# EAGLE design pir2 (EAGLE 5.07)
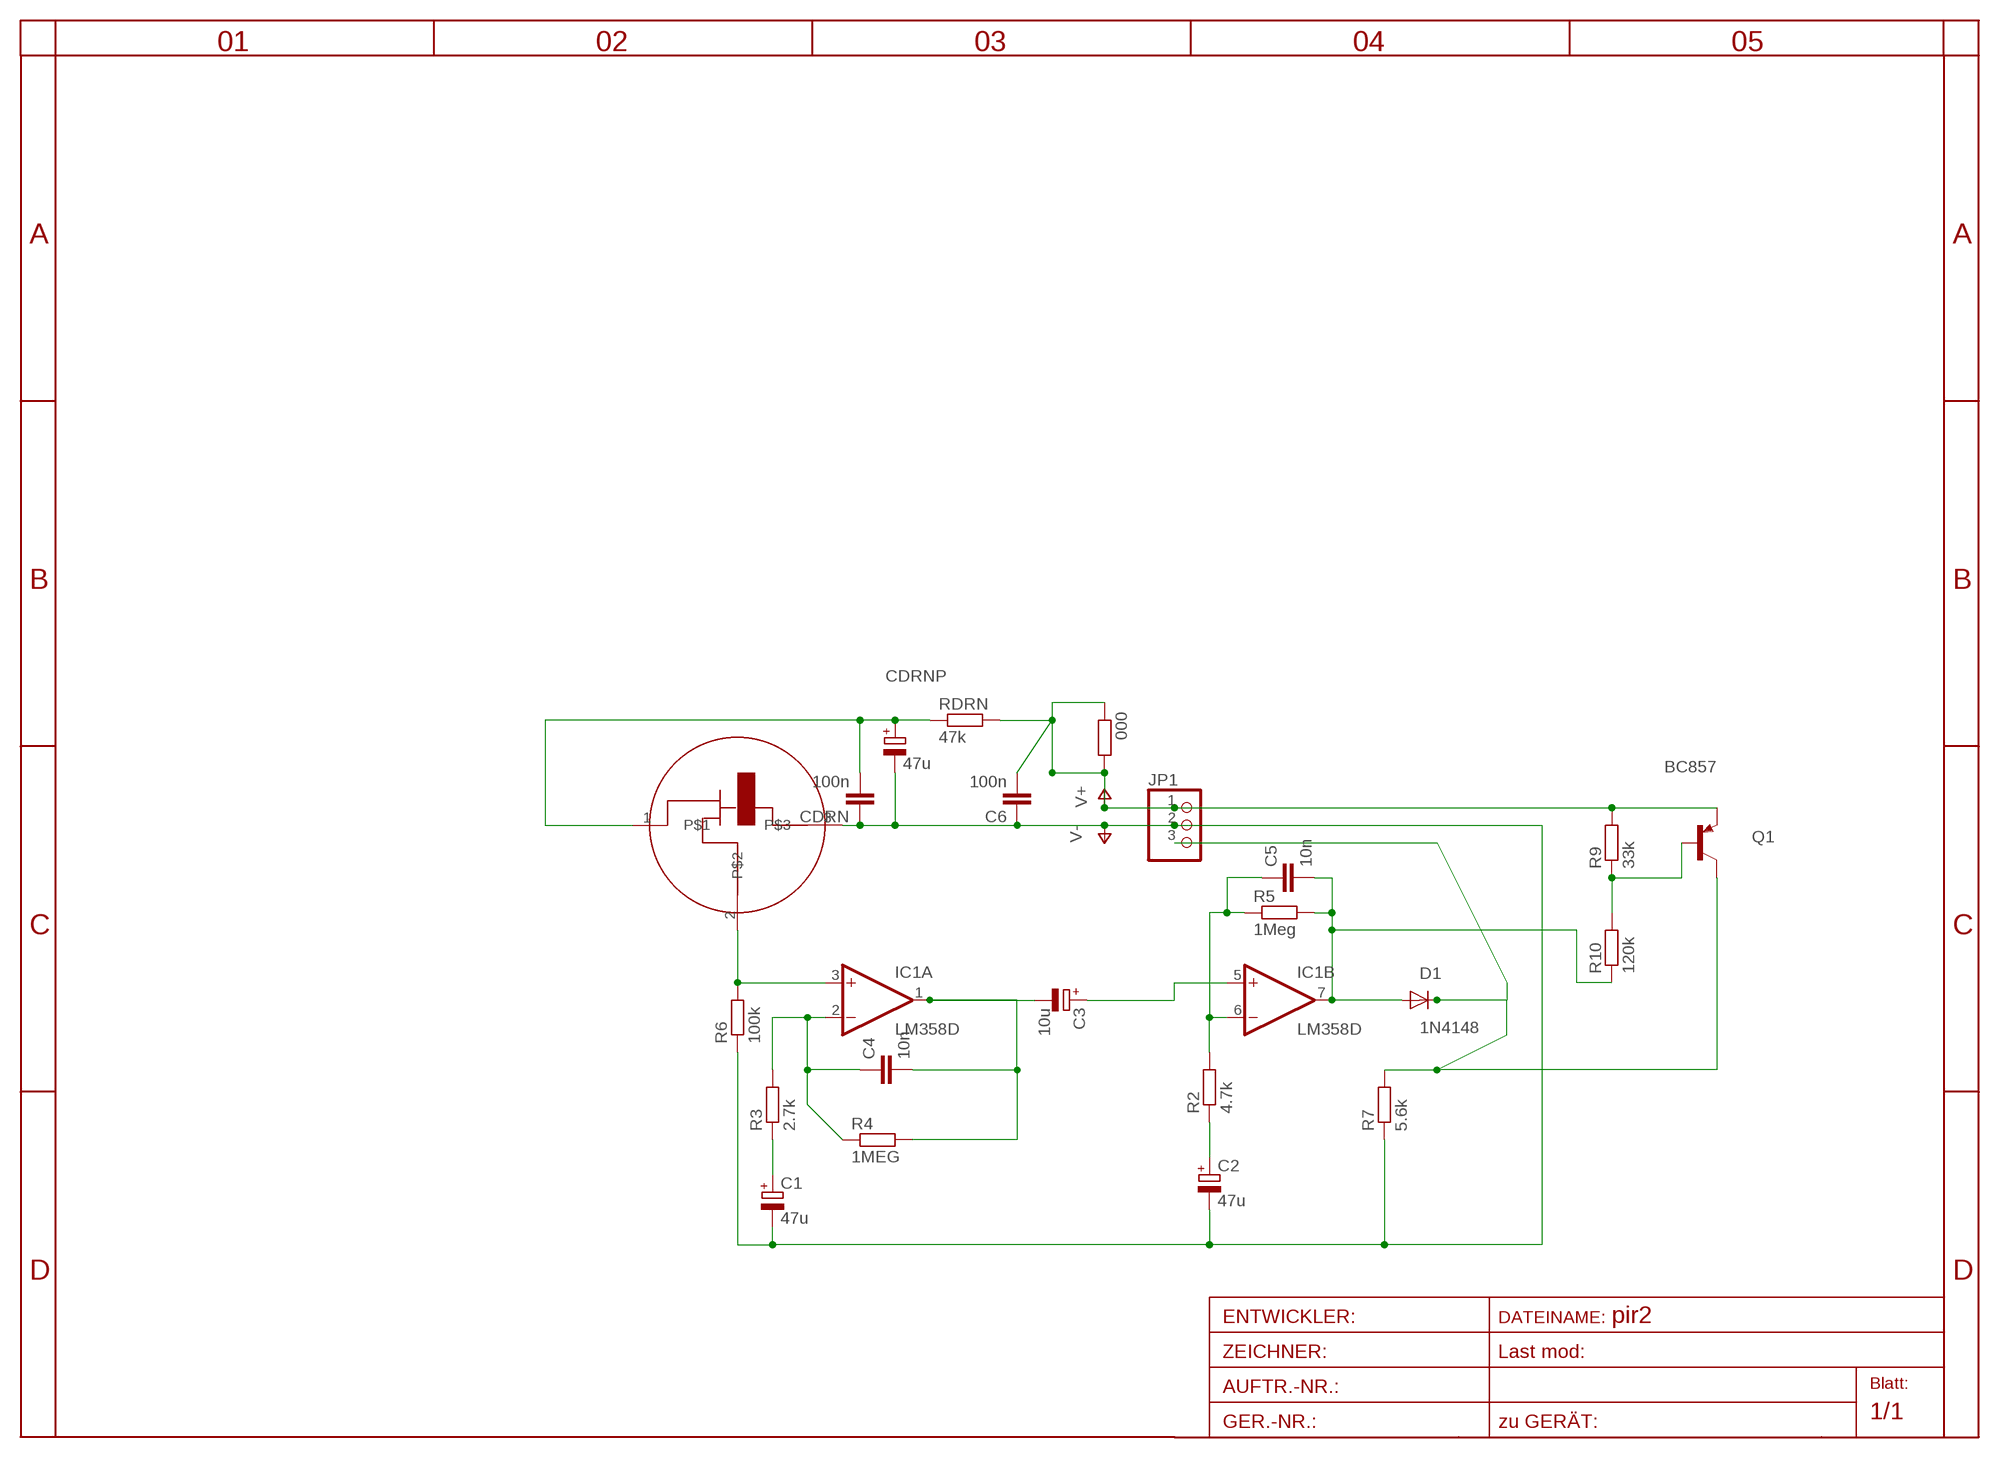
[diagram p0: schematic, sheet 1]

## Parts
000  R-EU_R1206  [R1206]
C1  47u  CPOL-EUTT2D4L  [TT2D4L]
C2  47u  CPOL-EUE2.5-5  [E2,5-5]
C3  10u  CPOL-EUE2.5-5  [E2,5-5]
C4  10n  C-EUC0805  [C0805]
C5  10n  C-EUC0805  [C0805]
C6  100n  C-EUC0805  [C0805]
CDRN  100n  C-EUC1206  [C1206]
CDRNP  47u  CPOL-EUE2.5-5  [E2,5-5]
D1  1N4148  1N4148MINIMELF  [MINIMELF]
IC1  LM358D  [SO08]
JP1  PINHD-1X3  [1X03]
PIR  RE200B  [R200B]
Q1  BC857  BC857ALT1SMD  [SOT23-BEC]
R2  4.7k  R-EU_R0805  [R0805]
R3  2.7k  R-EU_R1206  [R1206]
R4  1MEG  R-EU_R0805  [R0805]
R5  1Meg  R-EU_R0805  [R0805]
R6  100k  R-EU_R0805  [R0805]
R7  5.6k  R-EU_R0805  [R0805]
R9  33k  R-EU_R0805  [R0805]
R10  120k  R-EU_R1206  [R1206]
RDRN  47k  R-EU_R0805  [R0805]

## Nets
DRN: CDRN.2 CDRNP.+ PIR.1 RDRN.1
N$1: C5.2 D1.A IC1.7(B:OUT) R5.2 R10.1
N$4: IC1.3(A:+IN) PIR.2 R6.2
N$5: C4.1 IC1.2(A:-IN) R3.2 R4.1
N$6: C1.+ R3.1
N$7: C3.- C4.2 IC1.1(A:OUT) R4.2
N$8: C3.+ IC1.5(B:+IN)
N$9: C5.1 IC1.6(B:-IN) R2.2 R5.1
N$10: C2.+ R2.1
N$12: Q1.B R9.1 R10.2
SIGNAL: D1.C JP1.3 Q1.C R7.2
V+: 000.1 000.2 C6.2 JP1.1 Q1.E R9.2 RDRN.2
V-: C1.- C2.- C6.1 CDRN.1 CDRNP.- JP1.2 PIR.3 R6.1 R7.1

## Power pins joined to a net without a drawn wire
V+: IC1.8(P:V+)
V-: IC1.4(P:V-)

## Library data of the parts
000 R2-R7 R9 R10 RDRN = rcl:R-EU_: RESISTOR, European symbol
C1-C3 CDRNP = rcl:CPOL-EU: POLARIZED CAPACITOR, European symbol
C4-C6 CDRN = rcl:C-EU: CAPACITOR, European symbol
D1 = diode-1:1N4148: DIODE
IC1 = linear:LM358: OP AMP also LM158; LM258; LM2904 Source: http://cache.national.com/ds/LM/LM158.pdf
JP1 = pinhead:PINHD-1X3: PIN HEADER
PIR = photo-elements:RE200B
Q1 = transistor-pnp:BC857*: PNP Transistror

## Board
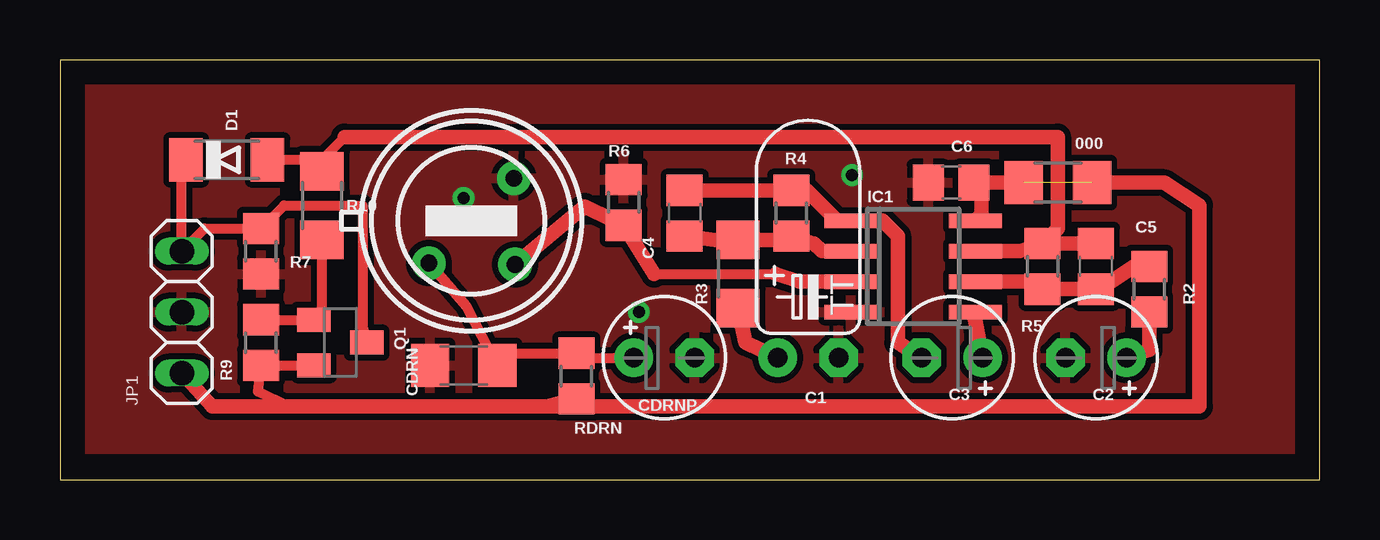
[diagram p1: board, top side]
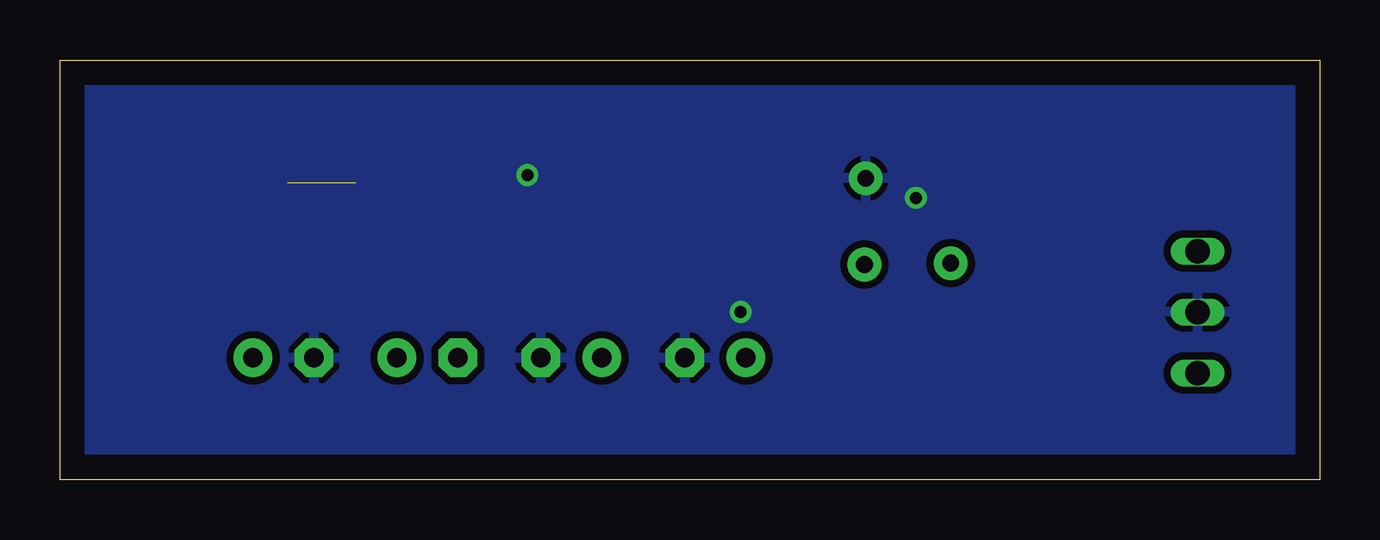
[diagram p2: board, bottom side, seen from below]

Size 52.5 x 17.5 mm. Coordinates in mm from the lower left corner, seen from the top.
Outline: 0,0 52.5,0 52.5,17.5 0,17.5 0,0
Copper layers (1*16): Top 0.035mm / dielectric 1.5mm / Bottom 0.035mm
Design rules "default": minimum track width 10mil, minimum drill 20mil, track to track 8mil, track to pad 8mil, pad to pad 8mil, via to via 8mil, smd to smd 8mil, copper to edge 40mil, drill to drill 8mil, minimum pad ring 1mil, minimum via ring 8mil, stop-mask expansion 4mil, vias tented up to drill 0mil, thermal gap 10mil

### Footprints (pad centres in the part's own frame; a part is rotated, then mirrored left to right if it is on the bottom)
R1206 = smd 1.6 x 1.803: 1 -1.422,0; 2 1.422,0
TT2D4L = drill 0.813 pad 1.6 round: + -1.27,0 | drill 0.813 pad 1.6 octagon: - 1.27,0
E2,5-5 = drill 0.813 pad 1.6 round: + -1.27,0 | drill 0.813 pad 1.6 octagon: - 1.27,0
C0805 = smd 1.3 x 1.5: 1 -0.95,0; 2 0.95,0
C1206 = smd 1.6 x 1.8: 1 -1.4,0; 2 1.4,0
MINIMELF = smd 1.4 x 1.8: A 1.7,0; C -1.7,0
SO08 = smd 0.6 x 2.2: 1 -1.905,-2.6; 2 -0.635,-2.6; 3 0.635,-2.6; 4 1.905,-2.6; 5 1.905,2.6; 6 0.635,2.6; 7 -0.635,2.6; 8 -1.905,2.6
1X03 = drill 1.016 long: 1 -2.54,0; 2 0,0; 3 2.54,0
R200B = drill 0.7 pad 1.4 round: 1 -2.5,0; 2 0,-2.58; 3 2.5,0
SOT23-BEC = smd 1 x 1.4: B -0.95,-1.1; C 0,1.1; E 0.95,-1.1
R0805 = smd 1.3 x 1.5: 1 -0.95,0; 2 0.95,0

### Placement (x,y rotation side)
000  41.59,12.38 180 top
C1  31.18,5.08 0 top
C2  43.18,5.08 180 top
C3  37.18,5.08 180 top
C4  26.04,11.11 90 top
C5  43.18,8.89 90 top
C6  37.15,12.38 0 top
CDRN  16.83,4.76 0 top
CDRNP  25.18,5.08 0 top
D1  6.95,13.34 0 top
IC1  35.56,8.89 270 top
JP1  5.08,6.99 90 top
PIR  17.14,10.79 45 top
Q1  11.68,5.71 270 top
R2  45.4,7.94 90 top
R3  28.26,8.57 90 top
R4  30.48,11.11 90 top
R5  40.96,8.89 90 top
R6  23.5,11.56 270 top
R7  8.38,9.53 90 top
R9  8.38,5.71 270 top
R10  10.92,11.43 270 top
RDRN  21.53,4.32 270 top

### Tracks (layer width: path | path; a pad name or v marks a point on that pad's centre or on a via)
DRN
  Top 0.406: CDRNP.+ 21.71,5.08 RDRN.1 18.73,5.27 CDRN.2 16.96,7.21 PIR.1
N$1
  Top 0.406: R5.2 | D1.A 10.44,13.34 R10.1 10.92,13.35 11.86,14.29
  Top 0.61: C5.2 R5.2 41.59,10.47 41.59,14.29 11.86,14.29 | R5.2 40.01,9.53 IC1.7
N$4
  Top 0.406: 24.77,8.57 29.84,8.57
  Top 0.61: PIR.2 21.86,11.39 R6.2 24.77,8.57 | IC1.3 30.8,8.26 29.84,8.57
N$5
  Top 0.61: C4.1 28.41,9.85 R3.2 29.99,9.99 R4.1 31.43,9.85 31.75,9.53 IC1.2
N$6
  Top 0.61: C1.+ 28.57,5.71 R3.1
N$7
  Top 0.406: 32.38,10.79 IC1.1 | 31.11,12.06 30.8,12.06 R4.2
  Top 0.61: C3.- 34.92,5.71 34.92,10.16 34.29,10.79 IC1.1 | 31.11,12.06 32.38,10.79 | C4.2 R4.2
N$8
  Top 0.406: IC1.5 38.1,6.92
  Top 0.61: 38.1,6.92 C3.+
N$9
  Top 0.406: 40.64,8.26 R5.1 | C5.1 43.5,7.94 43.81,8.26 | 44.77,8.89 R2.2
  Top 0.61: IC1.6 40.64,8.26 | R5.1 C5.1 | 43.81,8.26 44.77,8.89
N$10
  Top 0.61: C2.+ 45.4,5.4 R2.1
N$12
  Top 0.406: R10.2 10.92,7.17 Q1.B R9.1
SIGNAL
  Top 0.406: Q1.C 12.61,6.35 12.61,11.43 9.34,11.43 R7.2 6.03,10.47 JP1.3 5.08,13.34 D1.C
V+  (1 unrouted)
  Top 0.406: 9.53,3.05 8.26,3.66 R9.2 Q1.E
  Top 0.61: JP1.1 6.35,3.05 9.53,3.05 20.32,3.05 | 20.32,3.05 47.5,3.05 47.5,11.43 46.04,12.38 000.1 | 20.32,3.05 RDRN.2 | 38.41,12.38 000.2 | C6.2 38.41,12.38 | 38.41,12.38 38.41,11.05 IC1.8
V-  (via drill 0.5)
  Top 0.406: C1.- 33.02,5.08 | IC1.4 33.02,6.92
  other vias: 33.02,12.7 24.13,6.99 16.83,11.75
  pour Top (isolate 0.254, rank 2): 0.64,16.51 52.07,16.51 52.07,1.27 0.64,1.27
  pour Bottom (isolate 0.305): 0.64,16.51 52.07,16.51 52.07,1.27 0.64,1.27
